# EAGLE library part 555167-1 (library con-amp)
AMP connector
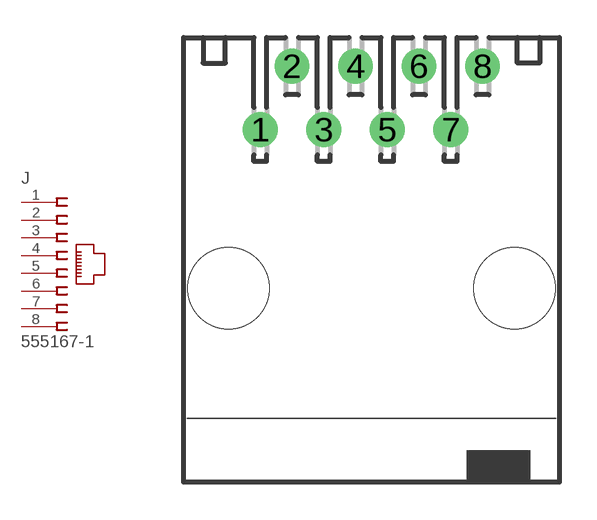
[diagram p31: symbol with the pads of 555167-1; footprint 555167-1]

Designator prefix J

## 555167-1 (MF: TYCO ELECTRONICS; MPN: 5555167-1; OC_FARNELL: 1557721; OC_NEWARK: 42K8765)  [555167-1]
1  1  pas
2  2  pas
3  3  pas
4  4  pas
5  5  pas
6  6  pas
7  7  pas
8  8  pas

## Footprint 555167-1 (pad centres in mm)
Modular Jack Keyed without Panel Stops
drill 0.889 round: 1 -4.445,5.207; 2 -3.175,7.747; 3 -1.905,5.207; 4 -0.635,7.747; 5 0.635,5.207; 6 1.905,7.747; 7 3.175,5.207; 8 4.445,7.747
hole 3.251 at -5.715,-1.143
hole 3.251 at 5.715,-1.143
